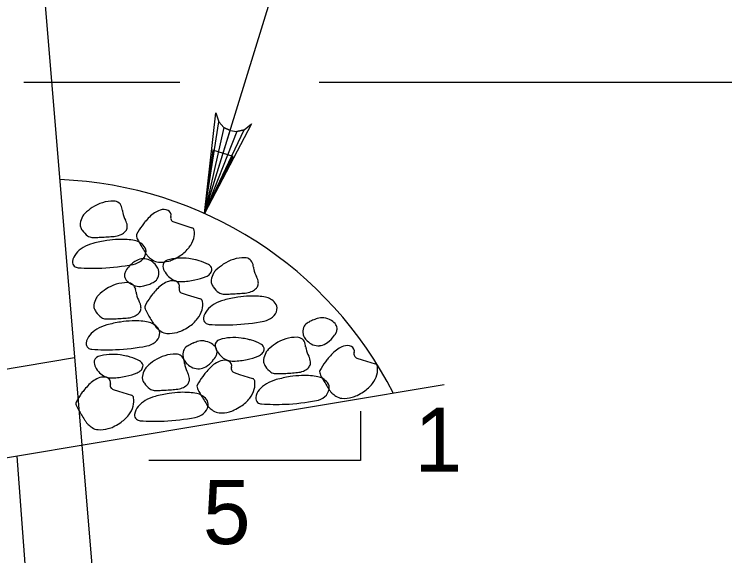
# Model space of a CAD drawing. Extents: x 638340 to 640242, y 295465 to 298435.
# Drawn here: x 639989.82 to 640023.07, y 298289.1 to 298314.42 of the extents above; entities that cross this region are included whole.
import ezdxf

# ---------------------------------------------------------------- set-up
doc = ezdxf.new("R2010")
doc.units = 0
for name, color, linetype in [('Level 4', 7, 'Continuous'), ('Level 6', 7, 'Continuous'), ('Level 8', 7, 'Continuous'), ('Level 9', 7, 'Continuous')]:
    doc.layers.add(name, color=color, linetype=linetype)

msp = doc.modelspace()

# ---------------------------------------------------------------- linework, layer by layer
at = {"layer": 'Level 4'}
for p, q in [((639998.716, 298305.109), (640004.965, 298325.275)), ((639990.271, 298311.252), (639997.573, 298311.252)), ((640004.092, 298311.252), (640050.155, 298311.252))]:
    msp.add_line(p, q, dxfattribs=at)
for points in [[(639998.716, 298305.109), (639999.259, 298309.811), (639999.392, 298309.395), (639999.633, 298309.127), (639999.916, 298308.983), (640000.23, 298308.942), (640000.584, 298309.025), (640000.927, 298309.295), (639998.716, 298305.109), (640000.584, 298309.025), (640000.23, 298308.942), (639998.716, 298305.109), (639999.916, 298308.983), (639999.633, 298309.127), (639998.716, 298305.109), (639999.392, 298309.395)], [(640006.019, 298295.863), (640006.019, 298293.561), (639996.115, 298293.561)]]:
    msp.add_lwpolyline(points, dxfattribs=at)
msp.add_lwpolyline([(640000.058, 298307.779), (639999.118, 298308.066), (639998.729, 298305.103)], close=True, dxfattribs=at)
at = {"layer": 'Level 6'}
msp.add_line((639989.943, 298293.758), (639995.084, 298225.283), dxfattribs=at)
at = {"layer": 'Level 8'}
for points in [[(639997.282, 298304.712), (639997.525, 298304.635), (639998.134, 298304.442)], [(639997.672, 298301.379), (639997.916, 298301.302), (639998.527, 298301.111)], [(640005.857, 298298.343), (640006.102, 298298.266), (640006.711, 298298.075)], [(640000.116, 298297.663), (640000.361, 298297.584), (640000.97, 298297.393)], [(639994.449, 298296.877), (639994.695, 298296.8), (639995.304, 298296.607)]]:
    msp.add_lwpolyline(points, dxfattribs=at)
for centre, radius, start, end in [((639994.462, 298303.913), 1.773, 89.5772, 124.1443), ((639994.473, 298305.292), 0.394, 11.4529, 89.5772), ((639993.466, 298304.735), 0.506, 132.7374, 153.538), ((639995.116, 298302.949), 2.938, 124.1443, 132.7374), ((639993.539, 298305.103), 1.346, 6.1004, 11.4529), ((639995.778, 298305.342), 0.905, 186.1004, 192.6291), ((639996.193, 298305.435), 1.331, 192.6291, 208.6753), ((639997.083, 298304.045), 1.296, 109.6635, 136.4562), ((639996.816, 298304.792), 0.502, 65.9597, 109.6635), ((639996.927, 298305.04), 0.231, 342.3569, 65.9597), ((639994.16, 298304.39), 1.281, 153.538, 168.4897), ((639994.417, 298304.463), 0.694, 6.391, 28.6753), ((640000.156, 298301.124), 5.536, 136.4562, 139.6491), ((639997.342, 298304.908), 0.205, 162.3569, 252.4715), ((639993.208, 298304.583), 0.31, 168.4897, 199.1639), ((639993.437, 298304.663), 0.553, 199.1639, 207.4728), ((639993.73, 298304.815), 0.882, 207.4728, 214.0468), ((639994.765, 298304.503), 0.344, 338.0834, 6.391), ((639998.599, 298302.514), 3.451, 144.1424, 152.1777), ((639998.068, 298302.898), 2.796, 139.6491, 144.1424), ((639998.089, 298304.302), 0.148, 9.0416, 72.4715), ((639993.872, 298304.911), 1.054, 214.0468, 234.0353), ((639994.399, 298305.05), 1.017, 275.2114, 291.5731), ((639994.507, 298304.778), 0.724, 291.5731, 310.9894), ((639994.737, 298304.514), 0.375, 310.9894, 338.0834), ((639995.667, 298304.062), 0.136, 152.1777, 193.5774), ((639997.31, 298304.178), 0.937, 344.9373, 9.0416), ((639993.468, 298304.355), 0.366, 234.0353, 268.2715), ((639993.559, 298307.352), 3.365, 268.2715, 270.9097), ((639995.169, 298297.452), 6.473, 99.0416, 104.9239), ((639993.473, 298312.715), 8.729, 270.9097, 272.5478), ((639993.226, 298318.274), 14.293, 272.5478, 273.846), ((639994.821, 298299.638), 4.259, 91.7881, 99.0416), ((639993.318, 298316.905), 12.921, 273.846, 275.2114), ((639994.819, 298299.702), 4.195, 86.0442, 91.7881), ((639994.915, 298301.087), 2.807, 79.021, 86.0442), ((639995.317, 298303.158), 0.697, 58.4341, 79.021), ((639996.004, 298304.143), 0.482, 193.5774, 207.4728), ((640001.324, 298306.909), 6.478, 207.4728, 211.2525), ((639995.2, 298302.969), 0.919, 40.5338, 58.4341), ((639997.11, 298304.232), 1.144, 321.7572, 344.9373), ((639993.739, 298302.343), 1.361, 120.8473, 139.2037), ((639993.967, 298301.962), 1.805, 104.9239, 120.8473), ((640010.586, 298312.53), 17.312, 211.2525, 212.2356), ((639995.621, 298303.329), 0.365, 349.0625, 40.5338), ((639996.632, 298304.608), 1.752, 303.0692, 321.7572), ((639993.247, 298302.768), 0.71, 139.2037, 172.3458), ((639995.388, 298303.374), 0.603, 309.5539, 349.0625), ((639999.131, 298305.307), 3.77, 212.2356, 214.3424), ((639996.492, 298303.503), 0.574, 214.3424, 227.6953), ((639997.297, 298304.388), 1.77, 227.6953, 235.2847), ((639996.083, 298305.452), 2.759, 295.7443, 303.0692), ((639992.787, 298302.83), 0.246, 172.3458, 230.2635), ((639996.148, 298301.764), 1.292, 117.4803, 136.4654), ((639995.216, 298303.581), 0.872, 280.7777, 309.5539), ((639995.869, 298302.299), 0.689, 91.376, 117.4803), ((639995.869, 298302.309), 0.68, 65.3457, 91.376), ((639995.828, 298302.219), 0.779, 41.057, 65.3457), ((639996.613, 298303.4), 0.568, 235.2847, 266.0442), ((639995.73, 298302.133), 0.909, 27.4728, 41.057), ((639996.673, 298304.266), 1.436, 266.0442, 285.2565), ((639997.051, 298302.66), 0.275, 106.8084, 186.6218), ((639997.643, 298300.7), 2.322, 81.3134, 106.8084), ((639996.696, 298304.181), 1.348, 285.2565, 295.7443), ((639997.065, 298296.916), 6.15, 78.4814, 81.3134), ((639997.838, 298300.711), 2.278, 73.8272, 78.4814), ((639997.879, 298300.852), 2.13, 61.1605, 73.8272), ((640001.249, 298300.298), 2.938, 124.1443, 132.7374), ((640000.595, 298301.263), 1.773, 89.5772, 124.1443), ((640000.605, 298302.641), 0.394, 11.4529, 89.5772), ((639992.829, 298302.88), 0.312, 230.2635, 266.2346), ((639993.487, 298312.882), 10.335, 266.2346, 272.3841), ((639993.498, 298312.606), 10.059, 272.3841, 280.7777), ((639995.392, 298302.213), 0.414, 149.2422, 171.9761), ((639996.152, 298301.761), 1.297, 136.4654, 149.2422), ((639996.14, 298302.347), 0.446, 8.0357, 27.4728), ((639996.013, 298302.329), 0.575, 337.0418, 8.0357), ((639997.358, 298302.696), 0.584, 186.6218, 200.3491), ((639997.476, 298302.74), 0.71, 200.3491, 212.797), ((639998.735, 298302.406), 0.356, 29.8544, 61.1605), ((639998.698, 298302.535), 0.375, 317.8475, 347.2445), ((639998.885, 298302.493), 0.183, 347.2445, 29.8544), ((639999.598, 298302.085), 0.506, 132.7374, 153.538), ((639999.672, 298302.452), 1.346, 6.1004, 11.4529), ((640001.911, 298302.692), 0.905, 186.1004, 192.6291), ((640002.326, 298302.785), 1.331, 192.6291, 208.6753), ((639995.318, 298302.223), 0.339, 171.9761, 209.5935), ((639996.171, 298302.262), 0.403, 299.831, 337.0418), ((639997.8, 298302.948), 1.095, 212.797, 230.2213), ((639997.615, 298302.726), 0.806, 230.2213, 250.5601), ((639997.628, 298305.043), 3.113, 281.8686, 292.039), ((639998.612, 298302.612), 0.49, 292.039, 317.8475), ((640000.292, 298301.739), 1.281, 153.538, 168.4897), ((640000.549, 298301.813), 0.694, 6.391, 28.6753), ((639995.104, 298300.099), 1.773, 89.5772, 124.1443), ((639995.544, 298302.352), 0.599, 209.5935, 237.6667), ((639995.115, 298301.478), 0.394, 11.4529, 89.5772), ((639995.771, 298302.709), 1.022, 237.6667, 259.0544), ((639994.577, 298306.338), 4.8, 285.7584, 288.5059), ((639995.701, 298302.981), 1.26, 288.5059, 293.8705), ((639995.753, 298302.865), 1.133, 293.8705, 297.4803), ((639995.043, 298304.229), 2.671, 297.4803, 299.831), ((639997.475, 298300.712), 1.296, 109.6635, 136.4562), ((639997.208, 298301.46), 0.502, 65.9597, 109.6635), ((639997.613, 298302.721), 0.8, 250.5601, 271.915), ((639997.318, 298301.708), 0.231, 342.3569, 65.9597), ((639997.518, 298305.569), 3.65, 271.915, 281.8686), ((639999.341, 298301.933), 0.31, 168.4897, 199.1639), ((639999.57, 298302.013), 0.553, 199.1639, 207.4728), ((639999.862, 298302.165), 0.882, 207.4728, 214.0468), ((640000.897, 298301.852), 0.344, 338.0834, 6.391), ((639995.758, 298299.135), 2.938, 124.1443, 132.7374), ((639994.181, 298301.289), 1.346, 6.1004, 11.4529), ((639996.42, 298301.528), 0.905, 186.1004, 192.6291), ((639995.702, 298302.354), 0.66, 259.0544, 285.7584), ((640000.548, 298297.792), 5.536, 136.4562, 139.6491), ((639997.733, 298301.576), 0.205, 162.3569, 252.4715), ((640000.004, 298302.261), 1.054, 214.0468, 234.0353), ((639999.601, 298301.704), 0.366, 234.0353, 268.2715), ((640000.532, 298302.4), 1.017, 275.2114, 291.5731), ((640000.639, 298302.128), 0.724, 291.5731, 310.9894), ((640000.869, 298301.864), 0.375, 310.9894, 338.0834), ((639994.802, 298300.576), 1.281, 153.538, 168.4897), ((639994.108, 298300.921), 0.506, 132.7374, 153.538), ((639996.835, 298301.621), 1.331, 192.6291, 208.6753), ((639998.991, 298299.182), 3.451, 144.1424, 152.1777), ((639998.46, 298299.566), 2.796, 139.6491, 144.1424), ((639998.481, 298300.97), 0.148, 9.0416, 72.4715), ((639999.691, 298304.702), 3.365, 268.2715, 270.9097), ((640001.301, 298294.801), 6.473, 99.0416, 104.9239), ((639999.606, 298310.065), 8.729, 270.9097, 272.5478), ((639999.358, 298315.623), 14.293, 272.5478, 273.846), ((640000.953, 298296.988), 4.259, 91.7881, 99.0416), ((639999.45, 298314.255), 12.921, 273.846, 275.2114), ((640000.951, 298297.051), 4.195, 86.0442, 91.7881), ((640001.047, 298298.436), 2.807, 79.021, 86.0442), ((640001.449, 298300.508), 0.697, 58.4341, 79.021), ((640001.333, 298300.319), 0.919, 40.5338, 58.4341), ((639993.85, 298300.77), 0.31, 168.4897, 199.1639), ((639995.059, 298300.65), 0.694, 6.391, 28.6753), ((639996.059, 298300.729), 0.136, 152.1777, 193.5774), ((639997.701, 298300.846), 0.937, 344.9373, 9.0416), ((639999.872, 298299.692), 1.361, 120.8473, 139.2037), ((640000.099, 298299.311), 1.805, 104.9239, 120.8473), ((640001.753, 298300.678), 0.365, 349.0625, 40.5338), ((639994.079, 298300.849), 0.553, 199.1639, 207.4728), ((639994.372, 298301.001), 0.882, 207.4728, 214.0468), ((639994.514, 298301.097), 1.054, 214.0468, 234.0353), ((639995.149, 298300.964), 0.724, 291.5731, 310.9894), ((639995.378, 298300.7), 0.375, 310.9894, 338.0834), ((639995.407, 298300.689), 0.344, 338.0834, 6.391), ((639996.395, 298300.81), 0.482, 193.5774, 207.4728), ((640001.716, 298303.577), 6.478, 207.4728, 211.2525), ((639997.501, 298300.9), 1.144, 321.7572, 344.9373), ((639999.379, 298300.118), 0.71, 139.2037, 172.3458), ((640001.52, 298300.723), 0.603, 309.5539, 349.0625), ((639994.11, 298300.541), 0.366, 234.0353, 268.2715), ((639994.201, 298303.539), 3.365, 268.2715, 270.9097), ((639994.115, 298308.902), 8.729, 270.9097, 272.5478), ((639993.868, 298314.46), 14.293, 272.5478, 273.846), ((639995.463, 298295.824), 4.259, 91.7881, 99.0416), ((639993.96, 298313.092), 12.921, 273.846, 275.2114), ((639995.041, 298301.237), 1.017, 275.2114, 291.5731), ((639995.461, 298295.888), 4.195, 86.0442, 91.7881), ((639995.557, 298297.273), 2.807, 79.021, 86.0442), ((640010.977, 298309.198), 17.312, 211.2525, 212.2356), ((639997.024, 298301.276), 1.752, 303.0692, 321.7572), ((639998.919, 298300.18), 0.246, 172.3458, 230.2635), ((639999.631, 298309.955), 10.059, 272.3841, 280.7777), ((640001.349, 298300.931), 0.872, 280.7777, 309.5539), ((640004.246, 298298.941), 1.26, 111.6288, 116.9933), ((640005.551, 298295.65), 4.8, 108.8812, 111.6288), ((640004.211, 298299.568), 0.66, 82.1773, 108.8812), ((640004.162, 298299.209), 1.022, 60.7895, 82.1773), ((640004.369, 298299.578), 0.599, 32.7163, 60.7895), ((639994.609, 298298.148), 1.805, 104.9239, 120.8473), ((639995.811, 298293.638), 6.473, 99.0416, 104.9239), ((639995.959, 298299.345), 0.697, 58.4341, 79.021), ((639995.842, 298299.155), 0.919, 40.5338, 58.4341), ((639999.523, 298301.975), 3.77, 212.2356, 214.3424), ((639996.883, 298300.171), 0.574, 214.3424, 227.6953), ((639997.689, 298301.056), 1.77, 227.6953, 235.2847), ((639996.263, 298299.515), 0.365, 349.0625, 40.5338), ((639996.474, 298302.12), 2.759, 295.7443, 303.0692), ((639998.961, 298300.23), 0.312, 230.2635, 266.2346), ((639999.619, 298310.232), 10.335, 266.2346, 272.3841), ((640003.899, 298299.575), 0.575, 160.1647, 191.1585), ((640003.738, 298299.634), 0.403, 122.9538, 160.1647), ((640004.971, 298297.731), 2.671, 120.6031, 122.9538), ((640004.188, 298299.055), 1.133, 116.9933, 120.6031), ((640004.587, 298299.719), 0.339, 355.0989, 32.7163), ((639993.888, 298298.954), 0.71, 139.2037, 172.3458), ((639994.381, 298298.529), 1.361, 120.8473, 139.2037), ((639996.03, 298299.56), 0.603, 309.5539, 349.0625), ((639997.004, 298300.068), 0.568, 235.2847, 266.0442), ((639997.064, 298300.933), 1.436, 266.0442, 285.2565), ((639997.087, 298300.849), 1.348, 285.2565, 295.7443), ((640003.773, 298299.551), 0.446, 191.1585, 210.5956), ((640003.73, 298300.135), 1.297, 319.5882, 332.365), ((640004.513, 298299.725), 0.414, 332.365, 355.0989), ((639995.858, 298299.768), 0.872, 280.7777, 309.5539), ((639999.937, 298294.572), 4.8, 108.8812, 111.6288), ((639998.597, 298298.49), 0.66, 82.1773, 108.8812), ((639998.548, 298298.131), 1.022, 60.7895, 82.1773), ((639999.495, 298298.942), 0.275, 106.8084, 186.6218), ((640000.087, 298296.982), 2.322, 81.3134, 106.8084), ((639999.509, 298293.199), 6.15, 78.4814, 81.3134), ((640000.282, 298296.993), 2.278, 73.8272, 78.4814), ((640000.323, 298297.134), 2.13, 61.1605, 73.8272), ((640003.039, 298297.545), 1.773, 89.5772, 124.1443), ((640003.049, 298298.924), 0.394, 11.4529, 89.5772), ((640004.171, 298299.786), 0.909, 210.5956, 224.1798), ((640004.078, 298299.696), 0.779, 224.1798, 248.4685), ((640003.734, 298300.132), 1.292, 300.6031, 319.5882), ((639993.429, 298299.016), 0.246, 172.3458, 230.2635), ((639993.471, 298299.066), 0.312, 230.2635, 266.2346), ((639994.129, 298309.068), 10.335, 266.2346, 272.3841), ((639994.14, 298308.792), 10.059, 272.3841, 280.7777), ((639998.123, 298298.556), 0.403, 122.9538, 160.1647), ((639999.357, 298296.653), 2.671, 120.6031, 122.9538), ((639998.574, 298297.977), 1.133, 116.9933, 120.6031), ((639998.632, 298297.863), 1.26, 111.6288, 116.9933), ((639998.754, 298298.5), 0.599, 32.7163, 60.7895), ((639999.802, 298298.978), 0.584, 186.6218, 200.3491), ((639999.92, 298299.022), 0.71, 200.3491, 212.797), ((639998.973, 298298.641), 0.339, 355.0989, 32.7163), ((640001.179, 298298.689), 0.356, 29.8544, 61.1605), ((640001.329, 298298.775), 0.183, 347.2445, 29.8544), ((640003.693, 298296.581), 2.938, 124.1443, 132.7374), ((640002.116, 298298.735), 1.346, 6.1004, 11.4529), ((640004.355, 298298.974), 0.905, 186.1004, 192.6291), ((640004.77, 298299.067), 1.331, 192.6291, 208.6753), ((640004.042, 298299.603), 0.68, 248.4685, 274.4988), ((640004.041, 298299.613), 0.689, 274.4988, 300.6031), ((640005.66, 298297.677), 1.296, 109.6635, 136.4562), ((640005.393, 298298.424), 0.502, 65.9597, 109.6635), ((640005.503, 298298.672), 0.231, 342.3569, 65.9597), ((639993.829, 298298.157), 0.275, 106.8084, 186.6218), ((639994.421, 298296.197), 2.322, 81.3134, 106.8084), ((639993.843, 298292.413), 6.15, 78.4814, 81.3134), ((639994.616, 298296.207), 2.278, 73.8272, 78.4814), ((639997.373, 298296.759), 1.773, 89.5772, 124.1443), ((639997.383, 298298.138), 0.394, 11.4529, 89.5772), ((639998.285, 298298.497), 0.575, 160.1647, 191.1585), ((639998.115, 298299.057), 1.297, 319.5882, 332.365), ((639998.899, 298298.647), 0.414, 332.365, 355.0989), ((640000.244, 298299.23), 1.095, 212.797, 230.2213), ((640000.072, 298301.325), 3.113, 281.8686, 292.039), ((640001.056, 298298.894), 0.49, 292.039, 317.8475), ((640001.142, 298298.817), 0.375, 317.8475, 347.2445), ((640002.736, 298298.021), 1.281, 153.538, 168.4897), ((640002.042, 298298.367), 0.506, 132.7374, 153.538), ((640002.993, 298298.095), 0.694, 6.391, 28.6753), ((640008.733, 298294.756), 5.536, 136.4562, 139.6491), ((640005.918, 298298.54), 0.205, 162.3569, 252.4715), ((639994.136, 298298.192), 0.584, 186.6218, 200.3491), ((639994.657, 298296.349), 2.13, 61.1605, 73.8272), ((639995.513, 298297.903), 0.356, 29.8544, 61.1605), ((639995.663, 298297.989), 0.183, 347.2445, 29.8544), ((639998.026, 298295.795), 2.938, 124.1443, 132.7374), ((639998.159, 298298.472), 0.446, 191.1585, 210.5956), ((639996.449, 298297.949), 1.346, 6.1004, 11.4529), ((639998.557, 298298.708), 0.909, 210.5956, 224.1798), ((639998.688, 298298.188), 0.905, 186.1004, 192.6291), ((639998.12, 298299.054), 1.292, 300.6031, 319.5882), ((639999.919, 298296.995), 1.296, 109.6635, 136.4562), ((639999.652, 298297.742), 0.502, 65.9597, 109.6635), ((640000.059, 298299.008), 0.806, 230.2213, 250.5601), ((640000.057, 298299.003), 0.8, 250.5601, 271.915), ((639999.762, 298297.99), 0.231, 342.3569, 65.9597), ((639999.962, 298301.851), 3.65, 271.915, 281.8686), ((640001.785, 298298.215), 0.31, 168.4897, 199.1639), ((640002.014, 298298.295), 0.553, 199.1639, 207.4728), ((640003.342, 298298.134), 0.344, 338.0834, 6.391), ((640007.176, 298296.146), 3.451, 144.1424, 152.1777), ((640006.645, 298296.53), 2.796, 139.6491, 144.1424), ((640006.666, 298297.934), 0.148, 9.0416, 72.4715), ((639994.254, 298298.236), 0.71, 200.3491, 212.797), ((639994.578, 298298.445), 1.095, 212.797, 230.2213), ((639995.39, 298298.109), 0.49, 292.039, 317.8475), ((639995.475, 298298.031), 0.375, 317.8475, 347.2445), ((639997.07, 298297.236), 1.281, 153.538, 168.4897), ((639996.376, 298297.581), 0.506, 132.7374, 153.538), ((639999.104, 298298.281), 1.331, 192.6291, 208.6753), ((639998.464, 298298.618), 0.779, 224.1798, 248.4685), ((639998.427, 298298.525), 0.68, 248.4685, 274.4988), ((639998.427, 298298.535), 0.689, 274.4988, 300.6031), ((640002.992, 298294.074), 5.536, 136.4562, 139.6491), ((640000.177, 298297.858), 0.205, 162.3569, 252.4715), ((640002.306, 298298.447), 0.882, 207.4728, 214.0468), ((640002.448, 298298.543), 1.054, 214.0468, 234.0353), ((640003.084, 298298.41), 0.724, 291.5731, 310.9894), ((640003.313, 298298.146), 0.375, 310.9894, 338.0834), ((640004.244, 298297.693), 0.136, 152.1777, 193.5774), ((640005.886, 298297.81), 0.937, 344.9373, 9.0416), ((639994.253, 298296.209), 1.296, 109.6635, 136.4562), ((639993.985, 298296.956), 0.502, 65.9597, 109.6635), ((639994.393, 298298.222), 0.806, 230.2213, 250.5601), ((639994.391, 298298.217), 0.8, 250.5601, 271.915), ((639994.096, 298297.204), 0.231, 342.3569, 65.9597), ((639994.296, 298301.065), 3.65, 271.915, 281.8686), ((639994.406, 298300.539), 3.113, 281.8686, 292.039), ((639996.118, 298297.429), 0.31, 168.4897, 199.1639), ((639997.327, 298297.309), 0.694, 6.391, 28.6753), ((640001.435, 298295.464), 3.451, 144.1424, 152.1777), ((640000.904, 298295.848), 2.796, 139.6491, 144.1424), ((640002.045, 298297.987), 0.366, 234.0353, 268.2715), ((640002.135, 298300.984), 3.365, 268.2715, 270.9097), ((640003.745, 298291.083), 6.473, 99.0416, 104.9239), ((640002.05, 298306.347), 8.729, 270.9097, 272.5478), ((640001.803, 298311.905), 14.293, 272.5478, 273.846), ((640003.398, 298293.27), 4.259, 91.7881, 99.0416), ((640001.895, 298310.537), 12.921, 273.846, 275.2114), ((640002.976, 298298.682), 1.017, 275.2114, 291.5731), ((640003.396, 298293.334), 4.195, 86.0442, 91.7881), ((640003.491, 298294.718), 2.807, 79.021, 86.0442), ((640003.893, 298296.79), 0.697, 58.4341, 79.021), ((640004.58, 298297.775), 0.482, 193.5774, 207.4728), ((640009.901, 298300.541), 6.478, 207.4728, 211.2525), ((640005.686, 298297.864), 1.144, 321.7572, 344.9373), ((639997.326, 298293.288), 5.536, 136.4562, 139.6491), ((639994.511, 298297.072), 0.205, 162.3569, 252.4715), ((639996.348, 298297.509), 0.553, 199.1639, 207.4728), ((639996.64, 298297.661), 0.882, 207.4728, 214.0468), ((639996.782, 298297.757), 1.054, 214.0468, 234.0353), ((639997.647, 298297.36), 0.375, 310.9894, 338.0834), ((639997.675, 298297.348), 0.344, 338.0834, 6.391), ((640000.925, 298297.252), 0.148, 9.0416, 72.4715), ((640000.145, 298297.128), 0.937, 344.9373, 9.0416), ((640002.316, 298295.975), 1.361, 120.8473, 139.2037), ((640002.543, 298295.593), 1.805, 104.9239, 120.8473), ((640003.777, 298296.601), 0.919, 40.5338, 58.4341), ((640019.162, 298306.162), 17.312, 211.2525, 212.2356), ((640004.197, 298296.96), 0.365, 349.0625, 40.5338), ((640005.208, 298298.24), 1.752, 303.0692, 321.7572), ((639995.238, 298295.062), 2.796, 139.6491, 144.1424), ((639996.378, 298297.201), 0.366, 234.0353, 268.2715), ((639996.469, 298300.198), 3.365, 268.2715, 270.9097), ((639996.384, 298305.561), 8.729, 270.9097, 272.5478), ((639996.136, 298311.12), 14.293, 272.5478, 273.846), ((639996.228, 298309.751), 12.921, 273.846, 275.2114), ((639997.31, 298297.896), 1.017, 275.2114, 291.5731), ((639997.417, 298297.624), 0.724, 291.5731, 310.9894), ((639998.503, 298297.011), 0.136, 152.1777, 193.5774), ((639998.839, 298297.093), 0.482, 193.5774, 207.4728), ((640004.16, 298299.859), 6.478, 207.4728, 211.2525), ((639999.945, 298297.182), 1.144, 321.7572, 344.9373), ((640001.823, 298296.4), 0.71, 139.2037, 172.3458), ((640003.964, 298297.006), 0.603, 309.5539, 349.0625), ((640007.708, 298298.939), 3.77, 212.2356, 214.3424), ((640005.068, 298297.135), 0.574, 214.3424, 227.6953), ((640004.659, 298299.084), 2.759, 295.7443, 303.0692), ((639995.769, 298294.678), 3.451, 144.1424, 152.1777), ((639995.259, 298296.466), 0.148, 9.0416, 72.4715), ((639994.479, 298296.342), 0.937, 344.9373, 9.0416), ((639996.877, 298294.808), 1.805, 104.9239, 120.8473), ((639998.079, 298290.298), 6.473, 99.0416, 104.9239), ((639997.731, 298292.484), 4.259, 91.7881, 99.0416), ((639997.729, 298292.548), 4.195, 86.0442, 91.7881), ((639997.825, 298293.933), 2.807, 79.021, 86.0442), ((639998.227, 298296.004), 0.697, 58.4341, 79.021), ((639998.111, 298295.815), 0.919, 40.5338, 58.4341), ((640013.421, 298305.48), 17.312, 211.2525, 212.2356), ((639999.468, 298297.558), 1.752, 303.0692, 321.7572), ((640001.363, 298296.462), 0.246, 172.3458, 230.2635), ((640003.793, 298297.213), 0.872, 280.7777, 309.5539), ((640005.874, 298298.02), 1.77, 227.6953, 235.2847), ((640005.189, 298297.032), 0.568, 235.2847, 266.0442), ((640005.249, 298297.897), 1.436, 266.0442, 285.2565), ((640005.272, 298297.813), 1.348, 285.2565, 295.7443), ((639992.837, 298296.226), 0.136, 152.1777, 193.5774), ((639993.173, 298296.307), 0.482, 193.5774, 207.4728), ((639998.493, 298299.073), 6.478, 207.4728, 211.2525), ((639994.279, 298296.396), 1.144, 321.7572, 344.9373), ((639996.649, 298295.189), 1.361, 120.8473, 139.2037), ((639998.298, 298296.22), 0.603, 309.5539, 349.0625), ((640001.967, 298298.257), 3.77, 212.2356, 214.3424), ((639998.531, 298296.175), 0.365, 349.0625, 40.5338), ((639999.327, 298296.453), 0.574, 214.3424, 227.6953), ((639998.918, 298298.402), 2.759, 295.7443, 303.0692), ((640001.405, 298296.512), 0.312, 230.2635, 266.2346), ((640002.063, 298306.514), 10.335, 266.2346, 272.3841), ((640002.075, 298306.237), 10.059, 272.3841, 280.7777), ((639996.157, 298295.614), 0.71, 139.2037, 172.3458), ((639998.126, 298296.427), 0.872, 280.7777, 309.5539), ((640000.133, 298297.338), 1.77, 227.6953, 235.2847), ((639999.448, 298296.35), 0.568, 235.2847, 266.0442), ((639999.508, 298297.215), 1.436, 266.0442, 285.2565), ((639999.531, 298297.131), 1.348, 285.2565, 295.7443), ((640007.755, 298304.694), 17.312, 211.2525, 212.2356), ((639996.301, 298297.471), 3.77, 212.2356, 214.3424), ((639993.801, 298296.773), 1.752, 303.0692, 321.7572), ((639995.697, 298295.676), 0.246, 172.3458, 230.2635), ((639995.739, 298295.726), 0.312, 230.2635, 266.2346), ((639996.397, 298305.728), 10.335, 266.2346, 272.3841), ((639996.408, 298305.452), 10.059, 272.3841, 280.7777), ((639993.661, 298295.667), 0.574, 214.3424, 227.6953), ((639994.467, 298296.552), 1.77, 227.6953, 235.2847), ((639993.782, 298295.564), 0.568, 235.2847, 266.0442), ((639993.865, 298296.345), 1.348, 285.2565, 295.7443), ((639993.252, 298297.616), 2.759, 295.7443, 303.0692), ((639993.842, 298296.43), 1.436, 266.0442, 285.2565)]:
    msp.add_arc(centre, radius, start, end, dxfattribs=at)
at = {"layer": 'Level 9'}
for p, q in [((639985.386, 298385.435), (639996.718, 298249.445)), ((639992.642, 298298.356), (639966.902, 298294.066)), ((640009.934, 298297.089), (639966.902, 298289.918))]:
    msp.add_line(p, q, dxfattribs=at)
msp.add_arc((639991.248, 298288.407), 18.297, 26.9324, 87.7453, dxfattribs=at)

# ---------------------------------------------------------------- texts
at = {"layer": 'Level 4'}
for s, p in [('1', (640008.55, 298293.03)), ('5', (639998.646, 298289.647))]:
    msp.add_text(s, height=3, dxfattribs=at).set_placement(p)

doc.saveas('drawing.dxf')
